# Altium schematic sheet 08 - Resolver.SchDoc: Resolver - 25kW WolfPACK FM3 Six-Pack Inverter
size 431 x 279 mm; Date: 09/2024; DocumentNumber: CRD25DA12N-FMC; Revision: 2.0; SheetNumber: 8; SheetTotal: 9; SheetSize: B
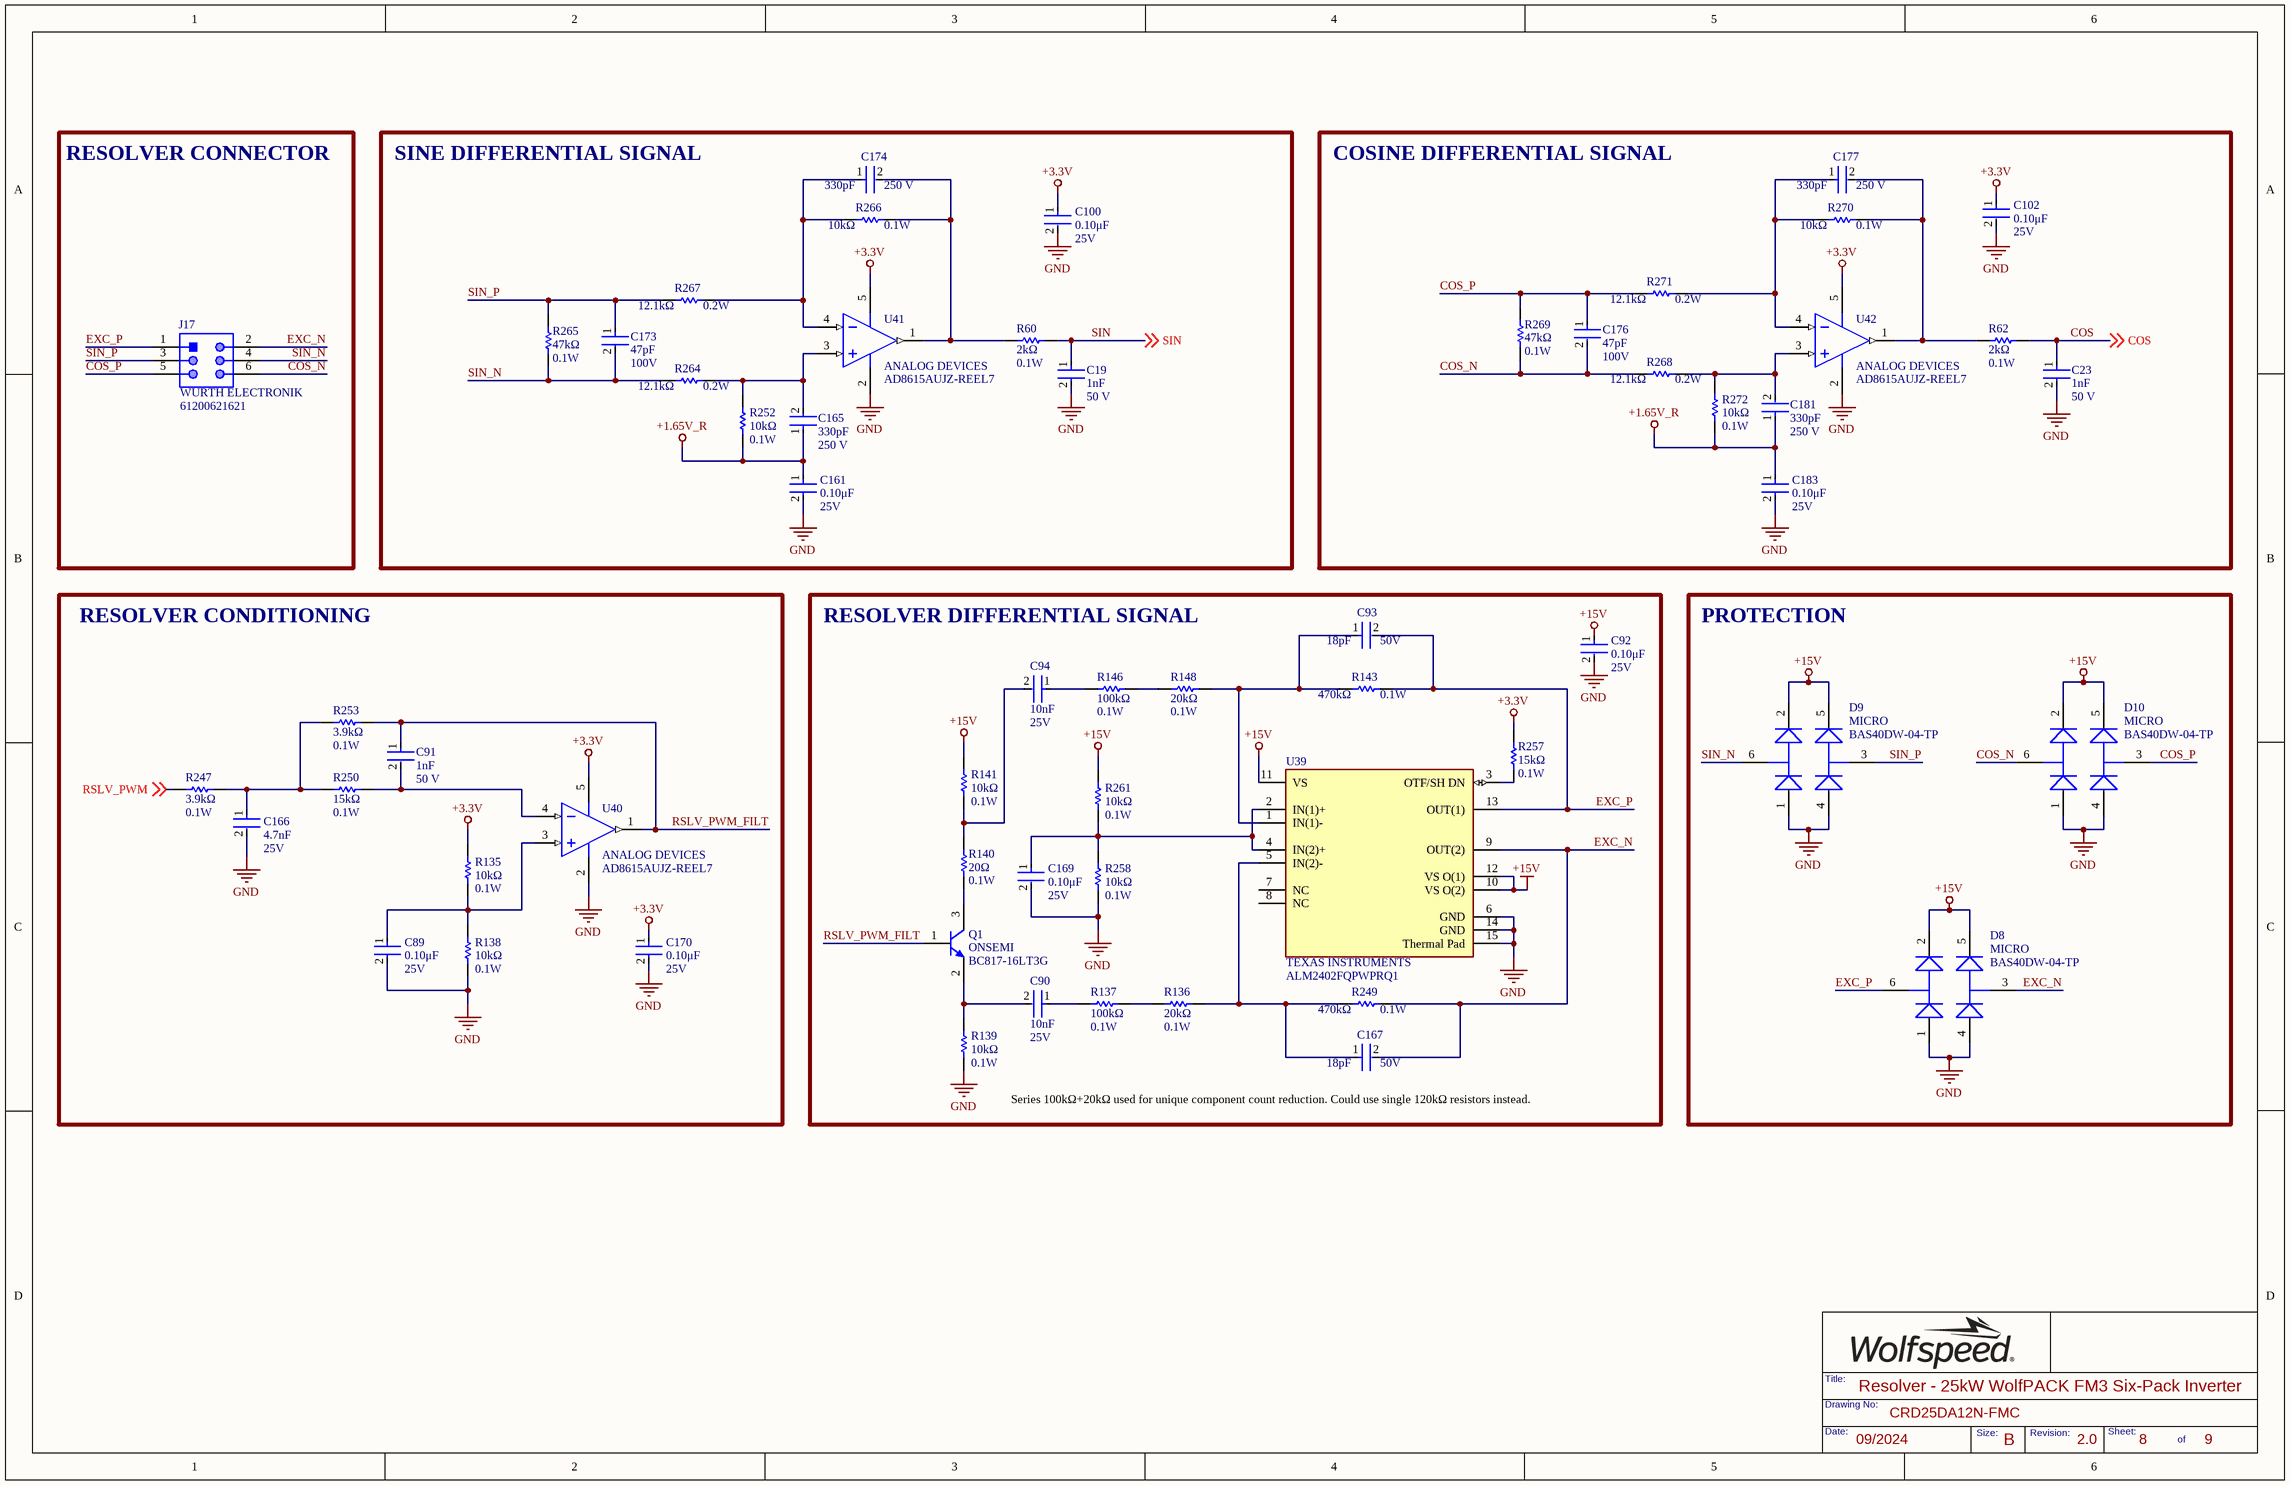
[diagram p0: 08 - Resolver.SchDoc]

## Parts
C19  Capacitance: 1nF  Voltage Rating: 50 V  [FP-C0603C-CF-IPC_B]  (hidden comment: C0603C102K5RACAUTO)
C23  Capacitance: 1nF  Voltage Rating: 50 V  [FP-C0603C-CF-IPC_B]  (hidden comment: C0603C102K5RACAUTO)
C89  Voltage Rating: 25V  Capacitance: 0.10μF  [FP-C0603C-CF-IPC_B]  (hidden comment: C0603C104K3RACTU)
C90  value 10nF  Voltage Rating: 25V  [FP-C0603C-CF-IPC_B]  (hidden comment: CL10B103KA8WPNC)
C91  Capacitance: 1nF  Voltage Rating: 50 V  [FP-C0603C-CF-IPC_B]  (hidden comment: C0603C102K5RACAUTO)
C92  Voltage Rating: 25V  Capacitance: 0.10μF  [FP-C0603C-CF-IPC_B]  (hidden comment: C0603C104K3RACTU)
C93  Capacitance: 18pF  Voltage Rating: 50V  [FP-C0603C-CF-IPC_B]  (hidden comment: 06035A180JAT2A)
C94  value 10nF  Voltage Rating: 25V  [FP-C0603C-CF-IPC_B]  (hidden comment: CL10B103KA8WPNC)
C100  Voltage Rating: 25V  Capacitance: 0.10μF  [FP-C0603C-CF-IPC_B]  (hidden comment: C0603C104K3RACTU)
C102  Voltage Rating: 25V  Capacitance: 0.10μF  [FP-C0603C-CF-IPC_B]  (hidden comment: C0603C104K3RACTU)
C161  Voltage Rating: 25V  Capacitance: 0.10μF  [FP-C0603C-CF-IPC_B]  (hidden comment: C0603C104K3RACTU)
C165  value 330pF  Voltage Rating: 250 V  [FP-C0603C-CF-IPC_B]  (hidden comment: C0603C331JAGAC7867)
C166  Voltage Rating: 25V  Capacitance: 4.7nF  [FP-C0603C-CF-IPC_B]  (hidden comment: C0603C472K3RAC7867)
C167  Capacitance: 18pF  Voltage Rating: 50V  [FP-C0603C-CF-IPC_B]  (hidden comment: 06035A180JAT2A)
C169  Voltage Rating: 25V  Capacitance: 0.10μF  [FP-C0603C-CF-IPC_B]  (hidden comment: C0603C104K3RACTU)
C170  Voltage Rating: 25V  Capacitance: 0.10μF  [FP-C0603C-CF-IPC_B]  (hidden comment: C0603C104K3RACTU)
C173  Capacitance: 47pF  Voltage Rating (DC): 100V  [FP-C0603C-CF-IPC_B]  (hidden comment: C0603C470J1GACTU)
C174  value 330pF  Voltage Rating: 250 V  [FP-C0603C-CF-IPC_B]  (hidden comment: C0603C331JAGAC7867)
C176  Capacitance: 47pF  Voltage Rating (DC): 100V  [FP-C0603C-CF-IPC_B]  (hidden comment: C0603C470J1GACTU)
C177  value 330pF  Voltage Rating: 250 V  [FP-C0603C-CF-IPC_B]  (hidden comment: C0603C331JAGAC7867)
C181  value 330pF  Voltage Rating: 250 V  [FP-C0603C-CF-IPC_B]  (hidden comment: C0603C331JAGAC7867)
C183  Voltage Rating: 25V  Capacitance: 0.10μF  [FP-C0603C-CF-IPC_B]  (hidden comment: C0603C104K3RACTU)
D8  Manufacturer Print: MICRO  [SOT65P222X120-6N]  (hidden comment: BAS40DW-04-TP)
D9  Manufacturer Print: MICRO  [SOT65P222X120-6N]  (hidden comment: BAS40DW-04-TP)
D10  Manufacturer Print: MICRO  [SOT65P222X120-6N]  (hidden comment: BAS40DW-04-TP)
J17  Manufacturer: WURTH ELECTRONIK  [61200621621]  (hidden comment: 61200621621)
Q1  Manufacturer: ONSEMI  [ONSC-SOT-23-3-318-08_V]  (hidden comment: BC817-16LT3G)
R60  Resistance: 2kΩ  Power Rating: 0.1W  [FP-MCR03-IPC_B]  (hidden comment: RT0603DRE072KL)
R62  Resistance: 2kΩ  Power Rating: 0.1W  [FP-MCR03-IPC_B]  (hidden comment: RT0603DRE072KL)
R135  Resistance: 10kΩ  Max Power Dissipation: 0.1W  [FP-MCR03-IPC_B]  (hidden comment: ERJ3EKF1002V)
R136  Resistance: 20kΩ  Power Rating: 0.1W  [FP-MCR03-IPC_B]  (hidden comment: CRCW060320K0FKTA)
R137  Resistance: 100kΩ  Power Rating: 0.1W  [FP-MCR03-IPC_B]  (hidden comment: RC0603FR-07100KL)
R138  Resistance: 10kΩ  Max Power Dissipation: 0.1W  [FP-MCR03-IPC_B]  (hidden comment: ERJ3EKF1002V)
R139  Resistance: 10kΩ  Max Power Dissipation: 0.1W  [FP-MCR03-IPC_B]  (hidden comment: ERJ3EKF1002V)
R140  Resistance: 20Ω  Power Rating: 0.1W  [FP-MCR03-IPC_B]  (hidden comment: RC0603JR-0720RL)
R141  Resistance: 10kΩ  Max Power Dissipation: 0.1W  [FP-MCR03-IPC_B]  (hidden comment: ERJ3EKF1002V)
R143  Resistance: 470kΩ  Power Rating: 0.1W  [FP-MCR03-IPC_B]  (hidden comment: RC0603FR-07470KL)
R146  Resistance: 100kΩ  Power Rating: 0.1W  [FP-MCR03-IPC_B]  (hidden comment: RC0603FR-07100KL)
R148  Resistance: 20kΩ  Power Rating: 0.1W  [FP-MCR03-IPC_B]  (hidden comment: CRCW060320K0FKTA)
R247  Resistance: 3.9kΩ  Power Rating: 0.1W  [FP-MCR03-IPC_B]  (hidden comment: ERJ3EKF3901V)
R249  Resistance: 470kΩ  Power Rating: 0.1W  [FP-MCR03-IPC_B]  (hidden comment: RC0603FR-07470KL)
R250  Resistance: 15kΩ  Power Rating: 0.1W  [FP-MCR03-IPC_B]  (hidden comment: ERA-3AED153V)
R252  Resistance: 10kΩ  Max Power Dissipation: 0.1W  [FP-MCR03-IPC_B]  (hidden comment: ERJ3EKF1002V)
R253  Resistance: 3.9kΩ  Power Rating: 0.1W  [FP-MCR03-IPC_B]  (hidden comment: ERJ3EKF3901V)
R257  Resistance: 15kΩ  Power Rating: 0.1W  [FP-MCR03-IPC_B]  (hidden comment: ERA-3AED153V)
R258  Resistance: 10kΩ  Max Power Dissipation: 0.1W  [FP-MCR03-IPC_B]  (hidden comment: ERJ3EKF1002V)
R261  Resistance: 10kΩ  Max Power Dissipation: 0.1W  [FP-MCR03-IPC_B]  (hidden comment: ERJ3EKF1002V)
R264  Resistance: 12.1kΩ  Max Power Dissipation: 0.2W  [FP-MCR03-IPC_B]  (hidden comment: ERJ-PB3B1212V)
R265  Resistance: 47kΩ  Power Rating: 0.1W  [FP-MCR03-IPC_B]  (hidden comment: RC0603FR-0747KL)
R266  Resistance: 10kΩ  Max Power Dissipation: 0.1W  [FP-MCR03-IPC_B]  (hidden comment: ERJ3EKF1002V)
R267  Resistance: 12.1kΩ  Max Power Dissipation: 0.2W  [FP-MCR03-IPC_B]  (hidden comment: ERJ-PB3B1212V)
R268  Resistance: 12.1kΩ  Max Power Dissipation: 0.2W  [FP-MCR03-IPC_B]  (hidden comment: ERJ-PB3B1212V)
R269  Resistance: 47kΩ  Power Rating: 0.1W  [FP-MCR03-IPC_B]  (hidden comment: RC0603FR-0747KL)
R270  Resistance: 10kΩ  Max Power Dissipation: 0.1W  [FP-MCR03-IPC_B]  (hidden comment: ERJ3EKF1002V)
R271  Resistance: 12.1kΩ  Max Power Dissipation: 0.2W  [FP-MCR03-IPC_B]  (hidden comment: ERJ-PB3B1212V)
R272  Resistance: 10kΩ  Max Power Dissipation: 0.1W  [FP-MCR03-IPC_B]  (hidden comment: ERJ3EKF1002V)
U39  Manufacturer: TEXAS INSTRUMENTS  [FP-PWP0014H-MFG]  (hidden comment: ALM2402FQPWPRQ1)
U40  Manufacturer: ANALOG DEVICES  [ADI-UJ-5_M]  (hidden comment: AD8615AUJZ-REEL7)
U41  Manufacturer: ANALOG DEVICES  [ADI-UJ-5_M]  (hidden comment: AD8615AUJZ-REEL7)
U42  Manufacturer: ANALOG DEVICES  [ADI-UJ-5_M]  (hidden comment: AD8615AUJZ-REEL7)

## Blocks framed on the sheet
RESOLVER CONNECTOR: J17
SINE DIFFERENTIAL SIGNAL: C19 C100 C161 C165 C173 C174 R60 R252 R264-R267 U41
COSINE DIFFERENTIAL SIGNAL: C23 C102 C176 C177 C181 C183 R62 R268-R272 U42
RESOLVER CONDITIONING: C89 C91 C166 C170 R135 R138 R247 R250 R253 U40
RESOLVER DIFFERENTIAL SIGNAL: C90 C92-C94 C167 C169 Q1 R136 R137 R139-R141 R143 R146 R148 R249 R257 R258 R261 U39
PROTECTION: D8-D10

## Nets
+1.65V_R: C161.1 C165.1 C181.1 C183.1 R252.1 R272.1
+3.3V: C100.1 C102.1 C170.1 R135.2 R257.2 U40.5(+V) U41.5(+V) U42.5(+V)
+15V: C92.1 D8.2(C1) D8.5(C2) D9.2(C1) D9.5(C2) D10.2(C1) D10.5(C2) R141.2 R261.2 U39.10(VS_O(2)) U39.11(VS) U39.12(VS_O(1))
GND: C19.2 C23.2 C89.2 C92.2 C100.2 C102.2 C161.2 C166.2 C169.2 C170.2 C183.2 D8.1(A1) D8.4(A2) D9.1(A1) D9.4(A2) D10.1(A1) D10.4(A2) R138.1 R139.1 R258.1 U39.6(GND) U39.14(GND) U39.15(Thermal_Pad) U40.2(-V) U41.2(-V) U42.2(-V)
COS: C23.1 R62.2 ; off-sheet COS
COS_N: C176.2 D10.6(AC1) J17.6 R268.1 R269.1
COS_P: C176.1 D10.3(AC2) J17.5 R269.2 R271.1
EXC_N: C167.2 D8.3(AC2) J17.2 R249.2 U39.9(OUT(2))
EXC_P: C93.2 D8.6(AC1) J17.1 R143.2 U39.13(OUT(1))
RSLV_PWM: R247.1 ; off-sheet RSLV_PWM
RSLV_PWM_FILT: C91.1 Q1.1(B) R253.2 U40.1(OUT)
SIN: C19.1 R60.2 ; off-sheet SIN
SIN_N: C173.2 D9.6(AC1) J17.4 R264.1 R265.1
SIN_P: C173.1 D9.3(AC2) J17.3 R265.2 R267.1
NetC89_1: C89.1 R135.1 R138.2 U40.3(+IN)
NetC90_1: C90.1 R137.2
NetC90_2: C90.2 Q1.2(E) R139.2
NetC91_2: C91.2 R250.1 U40.4(-IN)
NetC93_1: C93.1 R143.1 R148.1 U39.1(IN(1)-)
NetC94_1: C94.1 R146.2
NetC94_2: C94.2 R140.2 R141.1
NetC165_2: C165.2 R252.2 R264.2 U41.3(+IN)
NetC166_1: C166.1 R247.2 R250.2 R253.1
NetC167_1: C167.1 R136.1 R249.1 U39.5(IN(2)-)
NetC169_1: C169.1 R258.2 R261.1 U39.2(IN(1)+) U39.4(IN(2)+)
NetC174_1: C174.1 R266.2 R267.2 U41.4(-IN)
NetC174_2: C174.2 R60.1 R266.1 U41.1(OUT)
NetC177_1: C177.1 R270.2 R271.2 U42.4(-IN)
NetC177_2: C177.2 R62.1 R270.1 U42.1(OUT)
NetC181_2: C181.2 R268.2 R272.2 U42.3(+IN)
NetQ1_3: Q1.3(C) R140.1
NetR136_2: R136.2 R137.1
NetR146_1: R146.1 R148.2
NetR257_1: R257.1 U39.3(OTF/SH_DN)

Not connected (* = marked no-connect by the designer): U39 7(NC) 8(NC)

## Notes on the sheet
- (near C167) Series 100kΩ+20kΩ used for unique component count reduction. Could use single 120kΩ resistors instead.

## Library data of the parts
C19 C23 C91 = CMP-2006-03716-2: CAP CER 1000PF 50V X7R 0603; Manufacturer: KEMET; Material: Ceramic; Automotive Grade: Grade 1; Value: 1nF; Tolerance: 0.1; Temperature Coefficient: 30ppm/°C
C89 C92 C100 C102 C161 C169 C170 C183 = CMP-2006-03057-2: CAP CER 0.1UF 25V X7R 0603; Manufacturer: KEMET; Value: 0.10μF; Material: Ceramic; Tolerance: 0.1; Temperature Coefficient: 30ppm/°C; Automotive Grade: Grade 1
C90 C94 = CL10B103KA8WPNC: CAP CER 10000PF 25V X7R 0603; Manufacturer: SAMSUNG; Tolerance: 10%
C93 C167 = 06035A180JAT2A: CAP CER 18PF 50V C0G/NP0 0603; Manufacturer: KYOCERA AVX; Dielectric Material: Ceramic; Tolerance: 5%; Dielectric: C0G; Insulation Resistance: 100GR; Temperature Coefficient: 30ppm/°C
C165 C174 C177 C181 = CMP-03020-020944-2: CAP CER 330PF 250V C0G/NP0 0603; Manufacturer: KEMET; Material: Ceramic; Temperature Coefficient: 30ppm/°C; Tolerance: 0.05; Automotive Grade: Grade 1; Temperature Characteristic: C0G
C166 = C0603C472K3RAC7867: CAP CER 4700PF 25V 10% X7R 0603; Manufacturer: KEMET; Manufacturer Part Number: C0603C472K3RACTU; Dielectric Material: Ceramic; Value: 4.7nF
C173 C176 = C0603C470J1GACTU: CAP CER 47PF 100V C0G/NP0 0603; Manufacturer: KEMET; Dielectric Material: Ceramic; Tolerance: 5%; Dielectric: C0G; Temperature Coefficient: 30ppm/°C; Dissipation Factor: 0.1%
D8-D10 = BAS40DW-04-TP: DIODE ARRAY SCHOTTKY 40V SOT363; Manufacturer_Name: Micro Commercial Components (MCC); Manufacturer: MICRO COMMERCIAL; Class: DIO
J17 = CMP-1502-00000-1: CONN HEADER VERT 6POS 2.54MM; Withstanding Voltage: 500VAC; Working Voltage: 250VAC; Pin Number: 6; Gender: Male; Contact Resistance: 20mOhm
Q1 = CMP-1048-00731-1: TRANS NPN 45V 0.5A SOT23-3; IC Continuous (A): 0.5; Packing: Tape and Reel; fT Min (MHz): 100
R60 R62 = RT0603DRE072KL: RES SMD 2K OHM 0.5% 1/10W 0603; Manufacturer: YAGEO; Temperature Coefficient: 50ppm/°C; Voltage Rating: 75V; Max Power Dissipation: 100mW; Voltage Rating (DC): 50V; Value: 2kΩ
R135 R138 R139 R141 R252 R258 R261 R266 R270 R272 = ERJ3EKF1002V: RES SMD 10K OHM 1% 1/10W 0603; Manufacturer: PANASONIC; Manufacturer Part Number: ERJ-3EKF1002V; Temperature Coefficient: 100ppm/°C; Power Rating: 100mW; Voltage Rating: 75V; Value: 10kΩ
R136 R148 = CRCW060320K0FKTA: RES SMD 20K OHM 1% 1/10W 0603; Manufacturer: VISHAY DALE; Temperature Coefficient: 100ppm/°C; Voltage Rating: 75V; Max Power Dissipation: 100mW; Value: 20kΩ
R137 R146 = RC0603FR-07100KL: RES 100K OHM 1% 1/10W 0603; Manufacturer: YAGEO; Temperature Coefficient: 100ppm/°C; Voltage Rating: 50V; Working Voltage: 75V; Max Power Dissipation: 100mW; Value: 100kΩ
R140 = RC0603JR-0720RL: RES 20 OHM 5% 1/10W 0603; Manufacturer: YAGEO; Temperature Coefficient: 100ppm/°C; Voltage Rating (DC): 50V; Voltage Rating: 75V; Max Power Dissipation: 100mW; Value: 20Ω
R143 R249 = RC0603FR-07470KL: RES 470K OHM 1% 1/10W 0603; Manufacturer: YAGEO; Temperature Coefficient: 100ppm/°C; Voltage Rating: 50V; Max Power Dissipation: 100mW; Value: 470kΩ
R247 R253 = ERJ3EKF3901V: RES SMD 3.9K OHM 1% 1/10W 0603; Manufacturer: PANASONIC; Manufacturer Part Number: ERJ-3EKF3901V; Temperature Coefficient: 100ppm/°C; Voltage Rating: 75V; Max Power Dissipation: 100mW; Value: 3.9kΩ
R250 R257 = ERA-3AED153V: RES SMD 15K OHM 0.5% 1/10W 0603; Manufacturer: PANASONIC; Voltage Rating: 75V; Temperature Coefficient: 25ppm/°C; Max Power Dissipation: 100mW; Value: 15kΩ
R264 R267 R268 R271 = ERJ-PB3B1212V: RES SMD 12.1K OHM 0.1% 1/5W 0603; Manufacturer: PANASONIC; Temperature Coefficient: 50ppm/°C; Value: 12.1kΩ
R265 R269 = RC0603FR-0747KL: RES 47K OHM 1% 1/10W 0603; Manufacturer: YAGEO; Temperature Coefficient: 100ppm/°C; Voltage Rating: 50V; Max Power Dissipation: 100mW; Value: 47kΩ
U39 = CMP-04895-000282-1: IC POWER 2 CIRCUIT 14HTSSOP
U40-U42 = CMP-0384-02059-2: IC OPAMP GP 1 CIRCUIT TSOT23-5; Generic Part Number: AD8615; Iq/Amp: 1.7mA; V Span Max: 6V; Amplifiers Per Package: 1; Small Signal Bandwidth: 23MHz; Input Offset Voltage: 80uV; V Span Min: 2.7V; Slew Rate: 12V/us; Input Bias Current: 200fA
